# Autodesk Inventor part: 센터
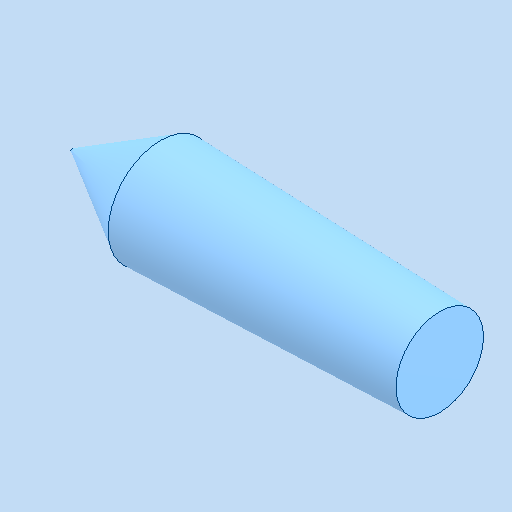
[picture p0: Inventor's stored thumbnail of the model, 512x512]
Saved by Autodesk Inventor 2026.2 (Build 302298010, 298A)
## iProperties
Created: 2026-08
Part Number: 센터
Material: 스테인리스강
Document SubType Name: Modeling
Designer: PC2-02
Density: 8.08 g/cm^3
Appearance: 기본값
Author: jhkim
Sending System: Autodesk Inventor 2027
Preprocessor: ST-DEVELOPER v20.1
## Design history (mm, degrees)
feature "솔리드1"
node "솔리드2"
